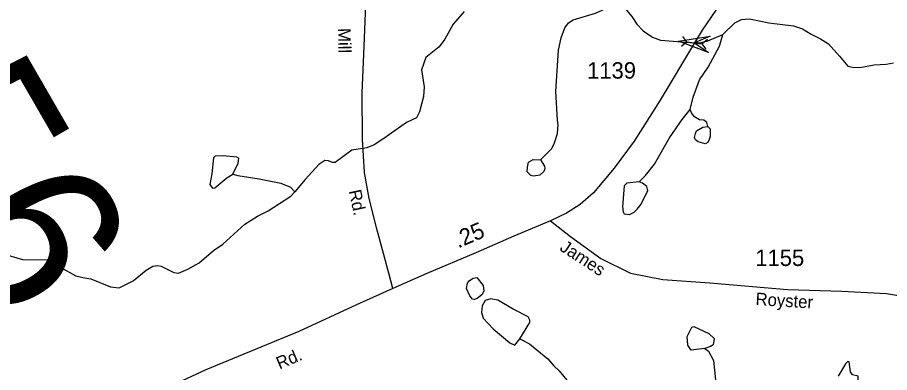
# Model space of a CAD drawing. Extents: x 2056842 to 2160602, y 826753 to 1016856.
# Drawn here: x 2083693 to 2090329, y 915800 to 918502 of the extents above; entities that cross this region are included whole.
import ezdxf

# ---------------------------------------------------------------- set-up
doc = ezdxf.new("R2010")
doc.units = 0
for name, color, linetype in [('Exist Hydrographic Creek Single Shore', 7, 'Continuous'), ('Exist Hydrographic Misc Water Feature', 7, 'Continuous'), ('Exist Road Secondary Mileage Hundredths English Label', 7, 'Continuous'), ('Exist Road Secondary Structure Pipe Attributed CELL', 7, 'Continuous'), ('Exist Road Secondary Structure Pipe CELL', 7, 'Continuous'), ('Exist Road Secondary Structure Pipe Number Label', 7, 'Continuous'), ('Exist Road Secondary Type 51 Attributed', 7, 'Continuous'), ('Exist Road Secondary Type 51 Label', 7, 'Continuous'), ('Exist Road Secondary Type 51 Number Label', 7, 'Continuous')]:
    doc.layers.add(name, color=color, linetype=linetype)

msp = doc.modelspace()

# ---------------------------------------------------------------- linework, layer by layer
at = {"layer": 'Exist Hydrographic Creek Single Shore'}
for points in [[(2088262.3, 918639.1), (2088368.9, 918509.6), (2088405.1, 918451.7), (2088455.2, 918399.8), (2088525.4, 918352.1), (2088585.3, 918328.2), (2088844.1, 918308.9), (2088883.5, 918309.2), (2088945.5, 918323.4), (2089061, 918371.8)], [(2087092.9, 918547.7), (2087007.2, 918451.5), (2086945.7, 918337.3), (2086901.8, 918277.2), (2086800.1, 918196.9), (2086768.3, 918102.8), (2086786.8, 917972.8), (2086783.1, 917900.8), (2086751.5, 917782.7), (2086729.5, 917738.7), (2086653.7, 917702.4), (2086482, 917579.9), (2086406.2, 917531.7), (2086350.2, 917509.4), (2086238.4, 917491.1), (2086110.7, 917398.7), (2086090.6, 917398.6), (2086058.6, 917410.5), (2086030.7, 917412.5), (2085986.8, 917382.3), (2085881, 917270), (2085803.3, 917173.8)], [(2089061, 918371.8), (2089152.7, 918460.2), (2089202.8, 918486.4), (2089262.6, 918490.4), (2089411, 918460.7), (2089598.8, 918437.5), (2089667, 918415.7), (2089733, 918374), (2089805.2, 918340), (2089865.4, 918300.4), (2089947.4, 918206.5), (2090011.8, 918130.7), (2090047.7, 918123), (2090103.8, 918121.2), (2090211.9, 918141.3), (2090303.9, 918147.6), (2090359.8, 918155.9)], [(2083575, 916706.8), (2083731.1, 916659.2), (2083915.2, 916657.9), (2083951.3, 916644), (2084017.3, 916602.2), (2084137.5, 916536.6), (2084189.6, 916522.7), (2084251.7, 916512.9), (2084401.8, 916453.3), (2084465.8, 916443.6), (2084573.6, 916497.9), (2084671.4, 916578.2), (2084723.3, 916608.3), (2084759.2, 916614.5), (2084787.3, 916608.6), (2084883.5, 916561), (2084919.3, 916557), (2084989.3, 916587.2), (2085075.2, 916633.5), (2085184.9, 916729.8), (2085256.7, 916778), (2085424.2, 916928.5), (2085519.9, 916990.9), (2085599.9, 917031.2), (2085773.6, 917141.7), (2085803.3, 917173.8)], [(2087516.7, 916057.3), (2087588.9, 916019.4), (2087729.2, 915904), (2087773.5, 915852.1), (2087815.5, 915812.2), (2087885.8, 915726.4), (2087940.4, 915578.7), (2088081.2, 915279.1), (2088103.6, 915159.2), (2088130.5, 914867.2), (2088142.6, 914813.3), (2088197.1, 914681.5), (2088271.3, 914557.7), (2088381.9, 914430.2), (2088457.9, 914378.4), (2088474.1, 914356.4), (2088502, 914346.5), (2088534, 914342.6)]]:
    msp.add_lwpolyline(points, dxfattribs=at)
at = {"layer": 'Exist Hydrographic Misc Water Feature'}
for points in [[(2087672.4, 917417.7), (2087760.1, 917503.9), (2087780, 917548), (2087801.8, 917620.1), (2087807.7, 917684), (2087803.6, 917720), (2087788.8, 917938), (2087809.8, 918254), (2087829.4, 918346.1), (2087857.3, 918422.1), (2087885.2, 918460.3), (2087921.1, 918484.4), (2088092.9, 918534.9), (2088192.8, 918579.2), (2088234.6, 918623.3), (2088262.5, 918639.4)], [(2088813.1, 917801.2), (2088834.8, 917895.2), (2088882.4, 918027.4), (2088950.1, 918123.7), (2089035.6, 918283.9), (2089061.4, 918372)], [(2088422.9, 917250.1), (2088472.7, 917300.2), (2088540.6, 917386.4), (2088654, 917586.7), (2088751.4, 917725), (2088813.1, 917801.2)], [(2088947.6, 917671.6), (2088939.4, 917703.6), (2088915.4, 917719.5), (2088883.4, 917723.4), (2088845.3, 917745.4), (2088821.3, 917775.3), (2088813.1, 917801.2)], [(2088851.8, 917619.4), (2088859.6, 917639.3), (2088907.6, 917667.5), (2088947.6, 917671.6)], [(2088947.6, 917671.6), (2088963.6, 917655.6), (2088963.8, 917595.7), (2088957.8, 917573.7)], [(2088957.8, 917573.7), (2088946, 917551.6), (2088925.9, 917541.5), (2088874, 917555.5), (2088853.9, 917571.4), (2088843.8, 917589.3), (2088851.8, 917619.4)], [(2085258.5, 917448), (2085196.6, 917445.8), (2085184.7, 917433.8), (2085170.9, 917311.8)], [(2085332.9, 917310.2), (2085372.7, 917394.4), (2085376.6, 917430.4), (2085362.7, 917438.3), (2085258.5, 917448)], [(2087574.6, 917363.3), (2087582.6, 917401.4), (2087616.4, 917421.5), (2087672.4, 917417.7)], [(2087672.4, 917417.7), (2087702.7, 917369.7), (2087706.6, 917349.7), (2087698.8, 917329.7), (2087668.7, 917301.6)], [(2085170.9, 917311.8), (2085157.2, 917229.6), (2085177.5, 917201.8), (2085195.3, 917205.9), (2085285.2, 917282.1), (2085332.9, 917310.2)], [(2085332.9, 917310.2), (2085369, 917298.3), (2085533.1, 917274.9), (2085697.1, 917241.4), (2085769.3, 917209.7), (2085803.3, 917173.8)], [(2087668.7, 917301.6), (2087618.9, 917293.5), (2087598.8, 917299.4), (2087570.7, 917327.4), (2087574.6, 917363.3)], [(2088422.9, 917250.1), (2088330.8, 917241.7), (2088309.1, 917219.7), (2088297.6, 917061.7)], [(2088409.5, 917044), (2088439.5, 917080.1), (2088491.1, 917186.3), (2088482.9, 917216.2), (2088448.9, 917242.2), (2088422.9, 917250.1)], [(2088297.6, 917061.7), (2088301.7, 917023.7), (2088309.7, 917007.7), (2088349.7, 917003.8), (2088385.5, 917019.9), (2088409.5, 917044)], [(2087133.5, 916500), (2087161.2, 916518.1), (2087189.3, 916524.2), (2087237.5, 916462.3)], [(2087135.8, 916384), (2087109.5, 916440), (2087117.3, 916480), (2087133.5, 916500)], [(2087237.5, 916462.3), (2087241.6, 916418.4), (2087227.8, 916392.3), (2087191.7, 916364.2), (2087167.9, 916356.1), (2087155.8, 916358.1), (2087135.8, 916384)], [(2087464, 916283.1), (2087348, 916350.7), (2087295.7, 916360.5), (2087251.8, 916348.4), (2087228, 916308.4), (2087224.1, 916256.4), (2087236.2, 916214.3), (2087312.5, 916132.6)], [(2087516.7, 916057.3), (2087592.4, 916179.5), (2087592.2, 916199.5), (2087580.3, 916223.5), (2087464, 916283.1)], [(2087312.5, 916132.6), (2087440.9, 916027), (2087477, 916007.1), (2087516.7, 916057.3)], [(2088790.5, 916075.3), (2088824.4, 916145.3), (2088840.4, 916151.4), (2088954.6, 916097.8)], [(2088923, 915981.7), (2088820.9, 915969.4), (2088794.8, 916007.3), (2088790.5, 916075.3)], [(2088954.6, 916097.8), (2088994.6, 916059.9), (2088986.8, 916011.9), (2088966.9, 915997.9), (2088923, 915981.7)], [(2088923, 915981.7), (2088950.9, 915961.8), (2088989.2, 915891.9), (2089005.6, 915743.9), (2089048.3, 915546.1), (2089088.5, 915442.3), (2089112.9, 915318.4), (2089121.3, 915210.4), (2089099.5, 915130.3)], [(2090089.5, 915731.4), (2090091.4, 915771.4), (2090047.3, 915783.2), (2090031.3, 915805.3), (2090023.1, 915881.2), (2090011, 915885.1), (2089995.2, 915867.1), (2089937.4, 915773)]]:
    msp.add_lwpolyline(points, dxfattribs=at)
at = {"layer": 'Exist Road Secondary Structure Pipe Attributed CELL'}
msp.add_lwpolyline([(2088950.9, 918234.9), (2088722.8, 918320.9), (2088963.4, 918360.5), (2088844.1, 918308.9)], close=True, dxfattribs=at)
at = {"layer": 'Exist Road Secondary Structure Pipe CELL'}
for p, q in [((2088745.2, 918282.8), (2088784, 918315.6)), ((2088753.4, 918356.1), (2088784, 918315.6)), ((2088784, 918315.6), (2088904.2, 918302.2)), ((2088942.9, 918335), (2088904.2, 918302.2)), ((2088934.8, 918261.8), (2088904.2, 918302.2))]:
    msp.add_line(p, q, dxfattribs=at)
at = {"layer": 'Exist Road Secondary Type 51 Attributed'}
for points in [[(2086548.2, 916438.4), (2086519.5, 916555.2), (2086429.7, 916882.2), (2086369.6, 917123.9), (2086333.7, 917321.6), (2086317.5, 917576.7), (2086314.8, 917928), (2086327.4, 918219.1), (2086357, 918922.6), (2086388.4, 919484.1), (2086399.2, 919886.6), (2086418.1, 920417.6), (2086453.1, 920815.6), (2086474.6, 921164.2), (2086469.2, 921333.1), (2086443.2, 921490.4), (2086382.2, 921698.8), (2086310.3, 921860.5), (2086232.2, 921989), (2086106.5, 922141.7), (2085910.8, 922359.2), (2085808.4, 922459.8)], [(2090998.7, 919075.3), (2090773.4, 918954.1), (2090577.7, 918867.8), (2090412.5, 918801.3), (2090302.9, 918783.3), (2089978.8, 918778.9), (2089652, 918782.5), (2089438.3, 918777.1), (2089328.8, 918755.5), (2089192.3, 918690.8), (2089078.3, 918628.8), (2089006.5, 918558.7), (2088904.1, 918406), (2088844.1, 918308.9)], [(2088844.1, 918308.9), (2088583.6, 917871.4), (2088386.1, 917560.6), (2088232.6, 917354.8), (2088076.3, 917166.2), (2087975.8, 917078.1), (2087871.6, 917013.4), (2087748.6, 916955)], [(2087748.6, 916955), (2087471.2, 916837.3), (2087180.3, 916711.5), (2086806.8, 916553.4), (2086548.2, 916438.4)], [(2087748.6, 916955), (2087902, 916833.9), (2088131.8, 916668.6), (2088358.1, 916557.2), (2088604.1, 916508.7), (2088960.5, 916482.6), (2089553.1, 916432.3), (2089966.1, 916417.9), (2090306.4, 916402.6), (2090485.9, 916372.1)], [(2086548.2, 916438.4), (2086273.5, 916316.2), (2085832.7, 916112.3), (2085126.1, 915820.3), (2084874.7, 915703.5), (2084596.4, 915608.3), (2084286.6, 915533.7), (2084013.7, 915483.4), (2083814.4, 915470.8), (2083409.5, 915531), (2083053.9, 915579.5), (2082842.1, 915579.5), (2082723.5, 915557.9), (2082618.5, 915521.1), (2082289.9, 915397.1), (2081493.5, 915067.4), (2081227.8, 914950.6), (2081030.3, 914885.9), (2080879.4, 914864.3), (2080732.2, 914855.4), (2080615.5, 914855.4), (2080523, 914838.3)]]:
    msp.add_lwpolyline(points, dxfattribs=at)

# ---------------------------------------------------------------- texts
at = {"layer": 'Exist Road Secondary Mileage Hundredths English Label'}
msp.add_text('.25', height=125, rotation=23.26923, dxfattribs=at).set_placement((2087046.3, 916743.5))
at = {"layer": 'Exist Road Secondary Structure Pipe Number Label'}
msp.add_text('P256', height=1230.31, rotation=300, dxfattribs=at).set_placement((2081623.4, 919459.4))
at = {"layer": 'Exist Road Secondary Type 51 Label'}
for s, rotation, p in [('Mill', 270.99142, (2086132.7, 918420.4)), ('Rd.', 282.13777, (2086213.2, 917181.4)), ('James', 326.92034, (2087813.1, 916733.9)), ('Royster', 356.48861, (2089307.5, 916313.9)), ('Rd.', 23.02254, (2085686.7, 915822.5))]:
    msp.add_text(s, height=95, rotation=rotation, dxfattribs=at).set_placement(p)
at = {"layer": 'Exist Road Secondary Type 51 Number Label'}
for s, p in [('1139', (2088028.1, 918036.4)), ('1155', (2089307.9, 916610.6))]:
    msp.add_text(s, height=125, dxfattribs=at).set_placement(p)

doc.saveas('drawing.dxf')
